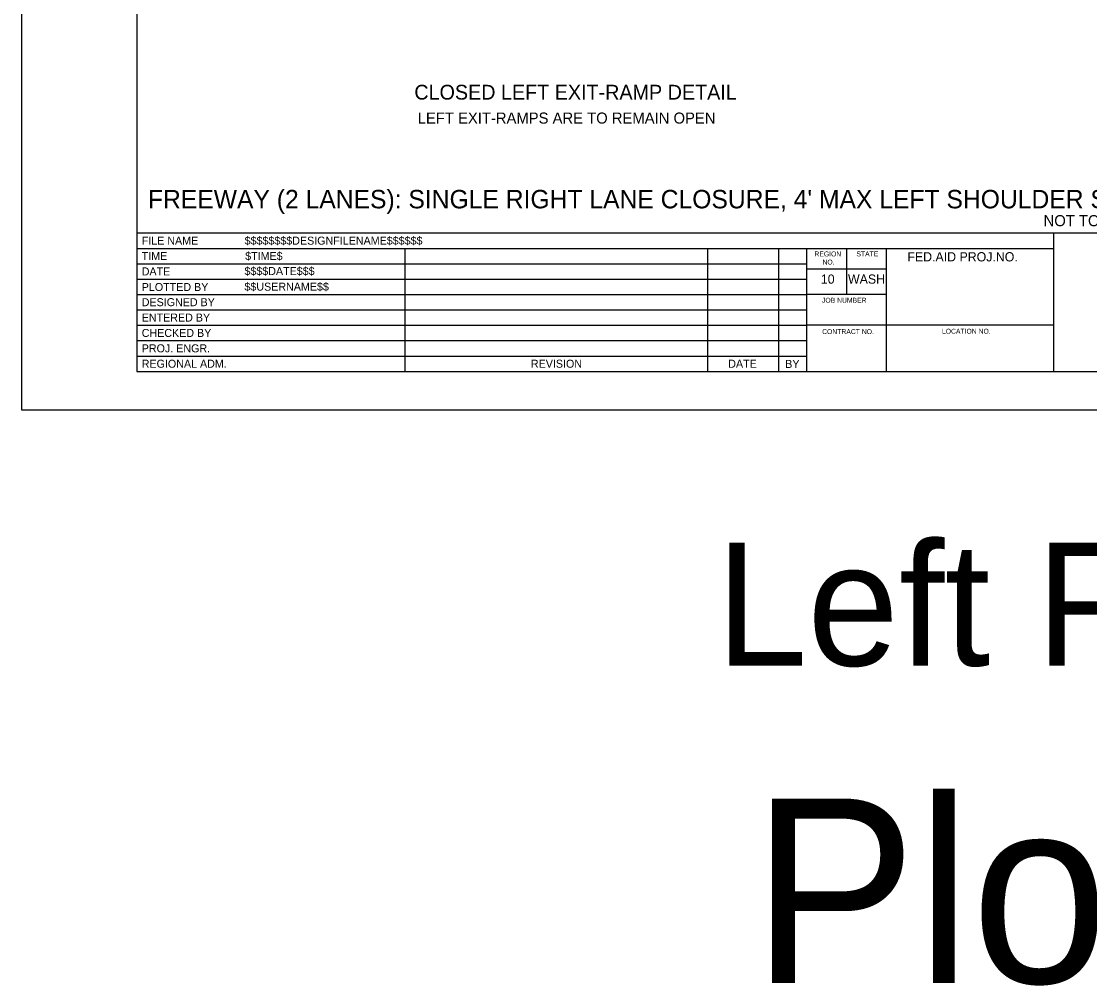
# Model space of a CAD drawing. Extents: x 99999 to 100116, y 99995 to 100013.
# Drawn here: x 100079.06 to 100087.75, y 99995.01 to 100002.85 of the extents above; entities that cross this region are included whole.
import ezdxf

# ---------------------------------------------------------------- set-up
doc = ezdxf.new("R2010")
doc.units = 0
for name, color, linetype in [('SH_DE_DetailHeading1Text', 7, 'Continuous'), ('SH_DE_DetailHeading2Text', 7, 'Continuous'), ('SH_GI_PlotLimits', 7, 'Continuous'), ('SH_GI_SheetBorder', 7, 'Continuous'), ('SH_GI_SheetLocationText', 7, 'Continuous'), ('SH_GI_SheetTextInCells', 7, 'Continuous'), ('SH_GI_TitleBlockText', 7, 'Continuous')]:
    doc.layers.add(name, color=color, linetype=linetype)

msp = doc.modelspace()

# ---------------------------------------------------------------- linework, layer by layer
at = {"layer": 'SH_GI_PlotLimits'}
msp.add_lwpolyline([(100079.0625, 99999.6875), (100096.0625, 99999.6875), (100096.0625, 100010.6875), (100079.0625, 100010.6875)], close=True, dxfattribs=at)
at = {"layer": 'SH_GI_SheetBorder'}
for p, q in [((100080, 100010.375), (100080, 100000)), ((100080, 100001.1259), (100095.75, 100001.1259)), ((100087.4566, 100000), (100087.4566, 100001.1259)), ((100080, 100001.0008), (100087.4566, 100001.0008)), ((100082.179, 100001.0008), (100082.179, 100000)), ((100084.641, 100001.0008), (100084.641, 100000)), ((100085.2164, 100001.0008), (100085.2164, 100000)), ((100085.4451, 100001.0008), (100085.4451, 100000)), ((100085.7719, 100000.6255), (100085.7719, 100001.0008)), ((100086.0956, 100000), (100086.0956, 100001.0008)), ((100080, 100000.8757), (100082.1821, 100000.8757)), ((100082.1821, 100000.8757), (100085.4466, 100000.8757)), ((100086.0958, 100000.831), (100085.4466, 100000.831)), ((100080, 100000.7506), (100082.1821, 100000.7506)), ((100082.1821, 100000.7506), (100085.4466, 100000.7506)), ((100080, 100000.6255), (100085.4466, 100000.6255)), ((100086.0958, 100000.6255), (100085.4466, 100000.6255)), ((100080, 100000.5004), (100085.4466, 100000.5004)), ((100080, 100000.3753), (100085.4466, 100000.3753)), ((100087.4566, 100000.3753), (100085.4466, 100000.3753)), ((100080, 100000.2502), (100085.4466, 100000.2502)), ((100080, 100000.1251), (100085.4466, 100000.1251)), ((100080, 100000), (100095.75, 100000))]:
    msp.add_line(p, q, dxfattribs=at)

# ---------------------------------------------------------------- texts
at = {"layer": 'SH_DE_DetailHeading1Text'}
for s, height, p in [("FREEWAY (2 LANES): SINGLE RIGHT LANE CLOSURE, 4' MAX LEFT SHOULDER SHIFT (55 MPH WORK ZONE SPEED LIMIT, 40 MPH ADVISORY SPEED)", 0.15, (100080.0913, 100001.3259)), ('NOT TO SCALE', 0.09, (100087.3727, 100001.1809))]:
    msp.add_text(s, height=height, rotation=360, dxfattribs=at).set_placement(p)
at = {"layer": 'SH_DE_DetailHeading2Text'}
for s, height, p in [('CLOSED LEFT EXIT-RAMP DETAIL', 0.12, (100082.2571, 100002.2105)), ('LEFT EXIT-RAMPS ARE TO REMAIN OPEN', 0.09, (100082.2845, 100002.0151))]:
    msp.add_text(s, height=height, rotation=360, dxfattribs=at).set_placement(p)
at = {"layer": 'SH_GI_SheetLocationText'}
for s, height, p in [('Left Ramps', 1, (100084.7087, 99997.6071)), ('Plot 5', 1.5, (100085.0007, 99995.0267))]:
    msp.add_text(s, height=height, dxfattribs=at).set_placement(p)
at = {"layer": 'SH_GI_SheetTextInCells'}
for s, height, p in [('FILE NAME', 0.06505, (100080.041, 100001.0308)), ('TIME', 0.06505, (100080.041, 100000.9057)), ('REGION', 0.04003, (100085.5099, 100000.9352)), ('STATE', 0.04003, (100085.8511, 100000.9357)), ('FED.AID PROJ.NO.', 0.07506, (100086.2652, 100000.8945)), ('NO.', 0.04003, (100085.5752, 100000.869)), ('DATE', 0.06505, (100080.041, 100000.7806)), ('10', 0.07506, (100085.5621, 100000.7131)), ('WASH', 0.07506, (100085.7826, 100000.7131)), ('PLOTTED BY', 0.06505, (100080.041, 100000.6538)), ('DESIGNED BY', 0.065052, (100080.041, 100000.5304)), ('JOB NUMBER', 0.04003, (100085.5712, 100000.5587)), ('ENTERED BY', 0.06505, (100080.041, 100000.4053)), ('CHECKED BY', 0.06505, (100080.041, 100000.2802)), ('CONTRACT NO.', 0.040032, (100085.5725, 100000.3037)), ('LOCATION NO.', 0.040032, (100086.5465, 100000.3067)), ('PROJ. ENGR.', 0.065052, (100080.041, 100000.1551)), ('REGIONAL ADM.', 0.065052, (100080.041, 100000.03)), ('REVISION', 0.06505, (100083.2048, 100000.03)), ('DATE', 0.06505, (100084.8091, 100000.03)), ('BY', 0.06505, (100085.2725, 100000.0285))]:
    msp.add_text(s, height=height, dxfattribs=at).set_placement(p)
at = {"layer": 'SH_GI_TitleBlockText'}
for s, height, p in [('$$$$$$$$DESIGNFILENAME$$$$$$', 0.065052, (100080.8775, 100001.0308)), ('$TIME$', 0.06505, (100080.882, 100000.9059)), ('$$$$DATE$$$', 0.065052, (100080.8759, 100000.7835)), ('$$USERNAME$$', 0.065052, (100080.8759, 100000.6567))]:
    msp.add_text(s, height=height, dxfattribs=at).set_placement(p)

doc.saveas('drawing.dxf')
